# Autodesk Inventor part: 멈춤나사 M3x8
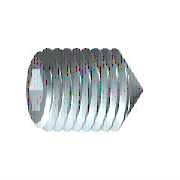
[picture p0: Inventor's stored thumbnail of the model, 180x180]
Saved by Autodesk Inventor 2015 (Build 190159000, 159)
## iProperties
Created: 2012-02
Part Number: 멈춤나사 M3x8
Material: 강철, 연강
Description: 6각 소켓 머리 없는 멈춤 나사
Document SubType Name: Modeling
Standard: KS B 1028
Designer: mduedu
Standards Organization: KS
Language: ko-KR
Size Designation: 원추점 M3x8
Categories: <MemberInstance><Categories><Category DisplayName="조임쇠" InternalName="e4da775c-781d-43d5-af7c-5136215cf5a6" Mnemonic="FSTN"><Category DisplayName="볼트" InternalN
Density: 7.86 g/cm^3
Mass: 0.360339 g
Surface Area: 0.888172 cm^2
Volume: 0.0458447 cm^3
Appearance: 강철
IsCustomPart: 1
Author: mduedu
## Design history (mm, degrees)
sketch "스케치1"
  geometry: L1 (0, 0)-(5.5, 0); L2 (8, 0.866)-(8, 1.5); L3 (8, 1.5)-(0, 1.5); L4 (8, 0.866)-(6, 0.866); L5 (6, 0.866)-(5.5, 0); L6 (0, -0.3)-(0, 1.8) reference; L7 (0, 1.5)-(0, 0)
  constraints: 13 end point, 3 parallel, 1 collinear, 1 perpendicular, 1 point on line
  dimensions: "d0" = 2 distance of L2.start L4.end (= INTI); "d1" = 60 deg angle of L5 L1; "d2" = 3 diameter of L3 L1 (= NND); "d3" = 1.73205 diameter of L4 L1 (= 1.1547 x SW); "d5" = 8 distance from line of L2 L3.end (= NLG)
revolve "본체" sketch "스케치1" stored, may be unused: angle "d6" = 90 deg
sketch "스케치2"
  geometry: L1 (-0.433, 0.75)-(0.433, 0.75); L2 (0.433, 0.75)-(0.866, 0); L3 (0.866, 0)-(0.433, -0.75); L4 (0.433, -0.75)-(-0.433, -0.75); L5 (-0.433, -0.75)-(-0.866, 0); L6 (-0.866, 0)-(-0.433, 0.75); 3 further points
  constraints: 12 end point, 1 coincident, 1 horizontal, 13 other
extrude "슬롯" join sketch "스케치2" taper "d7" = 0 deg; stored distance "d21" = 10
workaxis "Work Axis1"
workplane "Work Plane1"
sketch "스케치5"
  geometry: L1 (-4, -0.15)-(-2.65, -1.5) reference; L2 (-4, 0.15)-(-2.65, 1.5) reference; L3 (-2.65, 1.5)-(-4.15, 0); L4 (-2.65, -1.5)-(-4.15, 0); 1 further point
  constraints: 4 end point, 1 horizontal alignment, 1 perpendicular
node "작업점1"
body "Solid1"
feature "스레드" dims "d12" = 8 (= NLG), "d13" = 0
chamfer "모따기1" distance "d8" = 1.35 (computed from NND, SPD, FAWI); stored, may be unused: angle "d9" = 45 deg (= FAWI), second distance "d34" = 1.35 (computed from NND, SPD, FAWI)
chamfer "모따기2" distance "d10" = 0.30673 (= -0.5 x GD1 + 0.5 x NND); stored, may be unused: angle "d11" = 45 deg (= FAWI), second distance "d35" = 0.30673 (= -0.5 x GD1 + 0.5 x NND)
other parameters: "NND" = 3 [user parameter; used in 5 equation terms], "NLG" = 8 [user parameter; used in 2 equation terms], "INTI" = 2 [user parameter; used in 1 equation term], "FAWI" = 45 deg [user parameter; used in 4 equation terms], "SW" = 1.5 [user parameter; used in 2 equation terms], "GD1" = 2.38655 (= THREADDIA - 1.2269 x PTC) [user parameter; used in 2 equation terms], "d4" = 0, "FAWI1" = 45 deg [user parameter], "SPD" = 0.3 [user parameter; used in 2 equation terms], "d36" = 0, "d37" = 0, "GUL" = 0.30673 (= 0.61345 x PTC) [user parameter], "TOA" = 30 deg [user parameter], "THREADDIA" = 3 [user parameter; used in 1 equation term], "PTC" = 0.5 [user parameter; used in 4 equation terms], "GAL" = 0.30673 (= 0.61345 x PTC) [user parameter], "E0" = 1.7325 (= 1.155 x SW) [user parameter]
